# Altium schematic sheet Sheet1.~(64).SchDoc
size A3
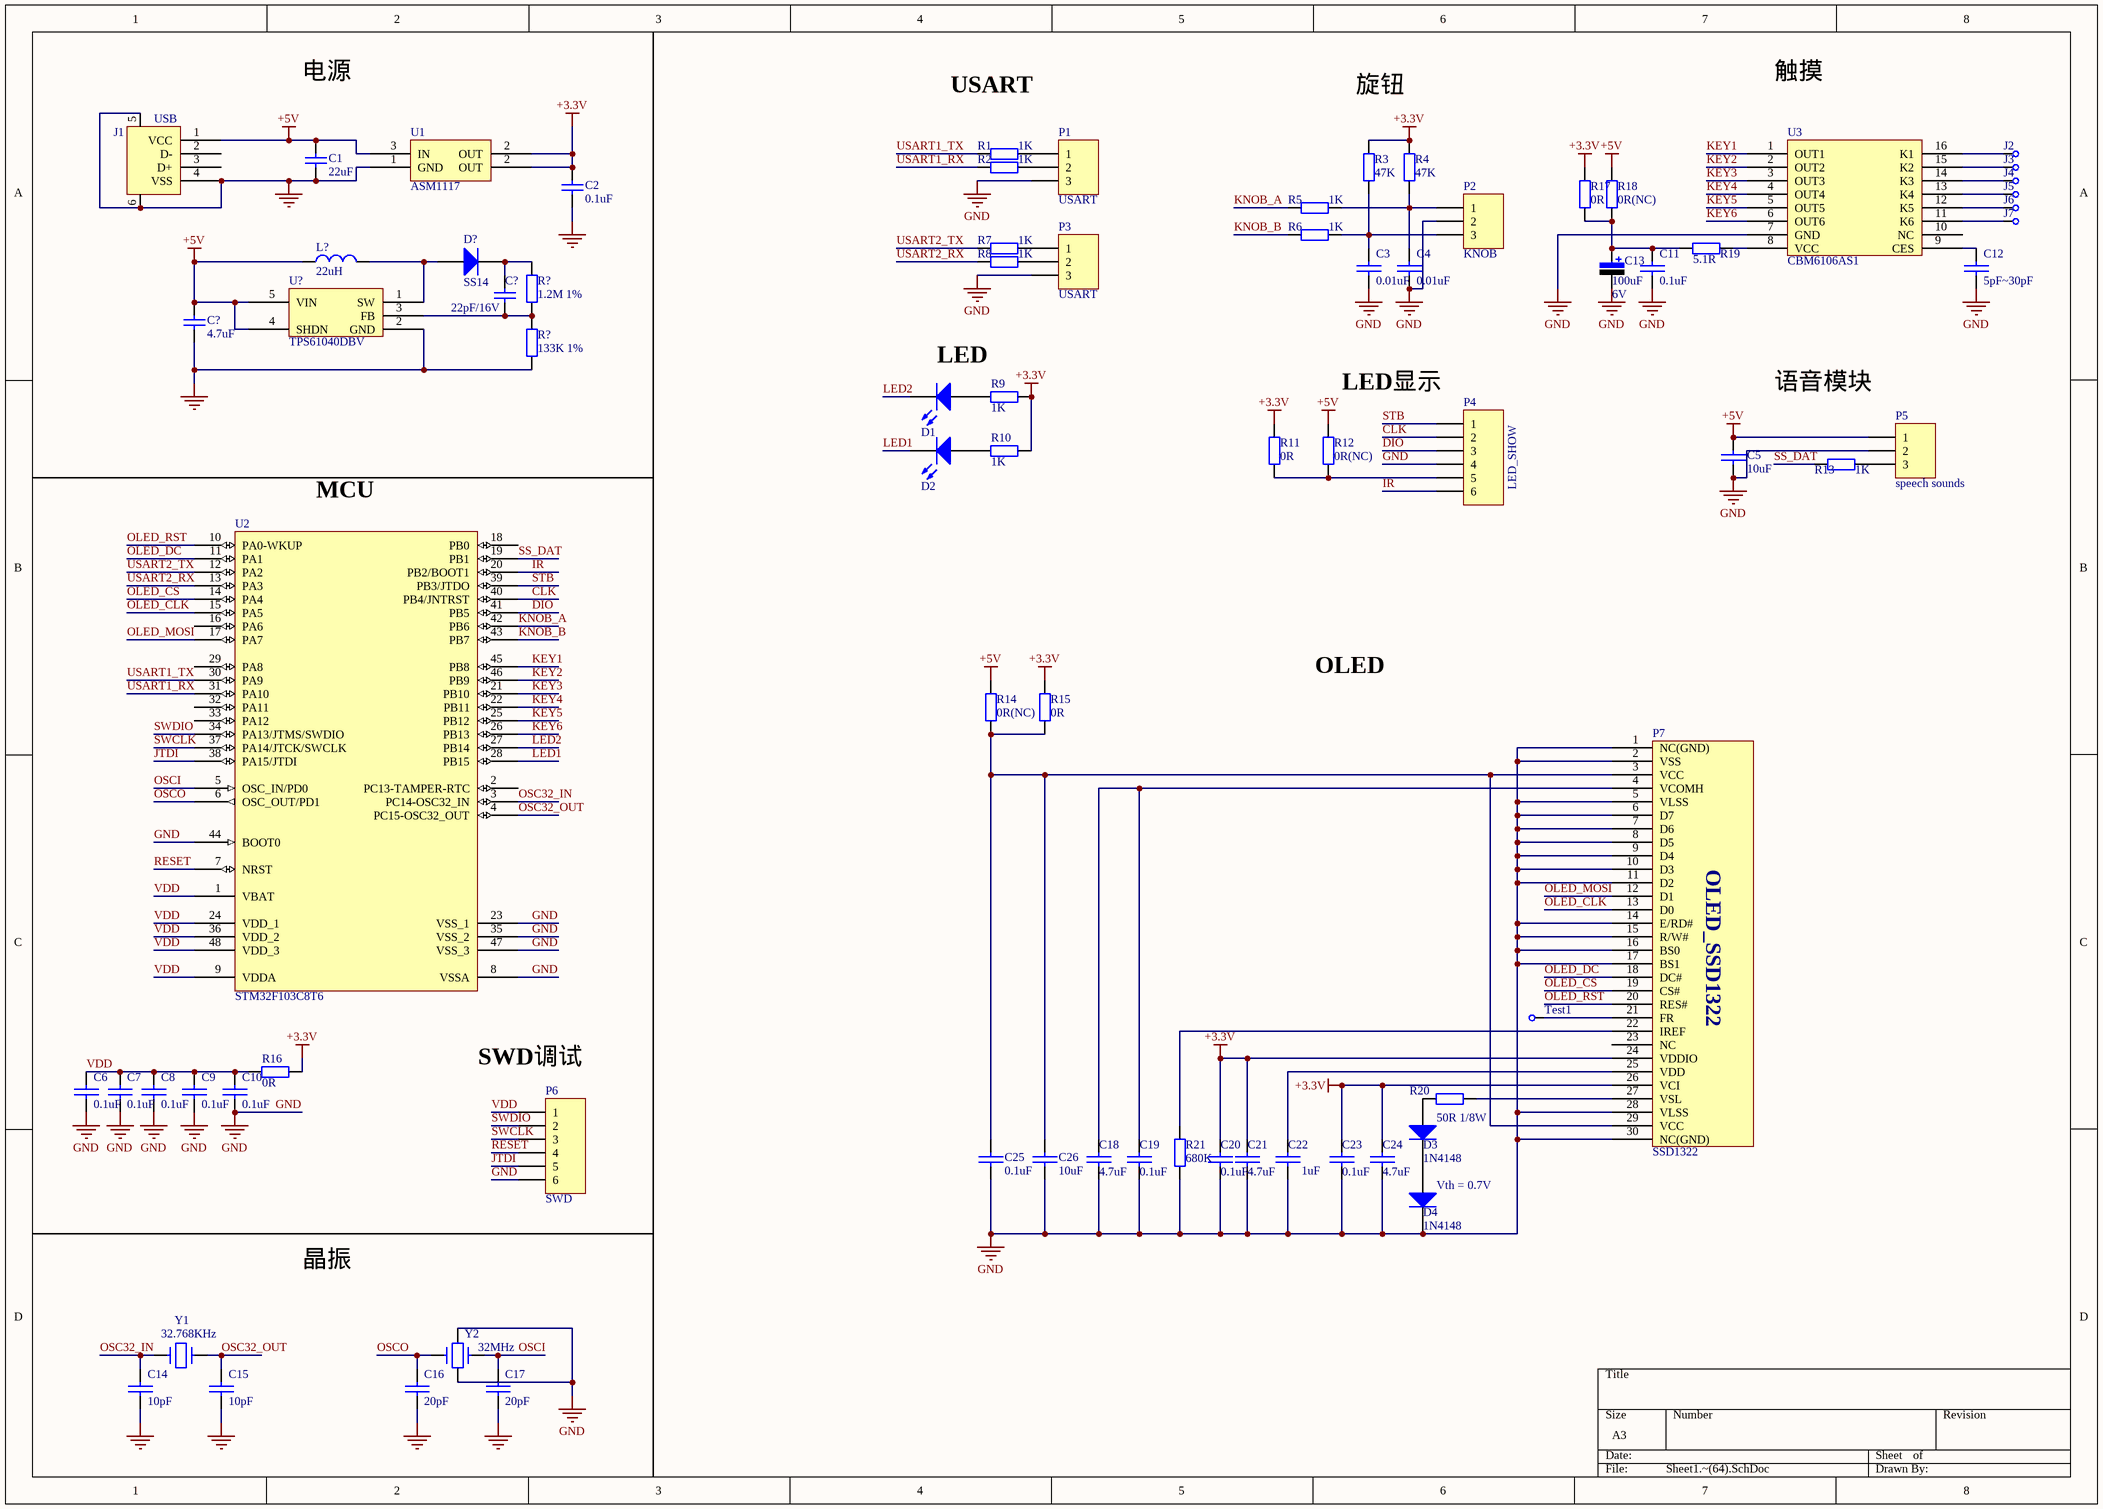
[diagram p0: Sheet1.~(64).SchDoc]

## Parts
(Parts that share a designator on the sheet are numbered #1, #2 ... from top to bottom, then left to right.)
C1  value 22uF  [0402C]  (hidden comment: Cap)
C2  value 0.1uF  [0402C]  (hidden comment: Cap)
C3  0.01uF  [0402C]
C4  0.01uF  [0402C]
C5  10uF  [0402C]
C6  0.1uF  [0402C]
C7  0.1uF  [0402C]
C8  0.1uF  [0402C]
C9  0.1uF  [0402C]
C10  0.1uF  [0402C]
C11  0.1uF  [0402C]
C12  5pF~30pF  [0402C]
C13  value 100uF  Vol: 6V  [CAP-3528]  (hidden comment: Cap Pol)
C14  10pF  [0402C]
C15  10pF  [0402C]
C16  20pF  [0402C]
C17  20pF  [0402C]
C18  4.7uF  [0402C]
C19  0.1uF  [0402C]
C20  0.1uF  [0402C]
C21  4.7uF  [0402C]
C22  1uF  [0402C]
C23  0.1uF  [0402C]
C24  4.7uF  [0402C]
C25  0.1uF  [0402C]
C26  10uF  [0402C]
C?#1  value 22pF/16V  [0402C]  (hidden comment: Cap)
C?#2  value 4.7uF  [0402C]  (hidden comment: Cap)
D1  LED0  [led0603]  (value not drawn)
D2  LED0  [led0603]  (value not drawn)
D3  Type: 1N4148  [DIODE-1206]  (hidden comment: Diode)
D4  Type: 1N4148  [DIODE-1206]  (hidden comment: Diode)
D?  Type: SS14  [DIODE-1206]  (hidden comment: Diode)
J1  USB  [USB_A1]
J2  CHECK  [CHECK-A]  (value not drawn)
J3  CHECK  [CHECK-A]  (value not drawn)
J4  CHECK  [CHECK-A]  (value not drawn)
J5  CHECK  [CHECK-A]  (value not drawn)
J6  CHECK  [CHECK-A]  (value not drawn)
J7  CHECK  [CHECK-A]  (value not drawn)
L?  value 22uH  [1206]  (hidden comment: Inductor)
P1  USART  [HDR3X1_A]
P2  KNOB  [HDR3X1_A]
P3  USART  [HDR3X1_A]
P4  LED_SHOW  [HDR6X1_B2]
P5  speech sounds  [HDR3X1_A]
P6  SWD  [HDR6X1_B2]
P7  SSD1322
R1  value 1K  [0402R]  (hidden comment: Res1)
R2  value 1K  [0402R]  (hidden comment: Res1)
R3  value 47K  [0603-1]  (hidden comment: Res1)
R4  value 47K  [0603-1]  (hidden comment: Res1)
R5  value 1K  [0603-1]  (hidden comment: Res1)
R6  value 1K  [0603-1]  (hidden comment: Res1)
R7  value 1K  [0402R]  (hidden comment: Res1)
R8  value 1K  [0402R]  (hidden comment: Res1)
R9  value 1K  [0402R]  (hidden comment: Res1)
R10  value 1K  [0402R]  (hidden comment: Res1)
R11  value 0R  [0402R]  (hidden comment: Res1)
R12  value 0R(NC)  [0402R]  (hidden comment: Res1)
R13  value 1K  [0402R]  (hidden comment: Res1)
R14  value 0R(NC)  [0402R]  (hidden comment: Res1)
R15  value 0R  [0402R]  (hidden comment: Res1)
R16  value 0R  [0402R]  (hidden comment: Res1)
R17  value 0R  [0402R]  (hidden comment: Res1)
R18  value 0R(NC)  [0402R]  (hidden comment: Res1)
R19  value 5.1R  [0603-1]  (hidden comment: Res1)
R20  value 50R 1/8W  [0402R]  (hidden comment: Res1)
R21  value 680K  [0402R]  (hidden comment: Res1)
R?#1  value 1.2M 1%  [0402R]  (hidden comment: Res1)
R?#2  value 133K 1%  [0402R]  (hidden comment: Res1)
Test1  CHECK  [CHECK-A]  (value not drawn)
U1  ASM1117  [SOT-223-3]
U2  STM32F103C8T6  [LQFP48_N]
U3  CBM6106AS1
U?  TPS61040DBV
Y1  32.768KHz  [SMD3215]
Y2  32MHz  [Y3225]

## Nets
+3.3V: C2.2 C20.1 C21.1 C23.1 C24.1 P7.24(VDDIO) P7.26(VCI) R3.2 R4.2 R9.1 R10.1 R11.1 R15.1 R16.2 R17.1 U1.2(OUT)
+5V: C1.2 C5.1 C?#2.2 J1.1(VCC) L?.1 P5.1 R12.1 R14.1 R18.1 U1.3(IN) U?.4(SHDN) U?.5(VIN)
GND: C1.1 C2.1 C3.2 C4.2 C5.2 C6.2 C7.2 C8.2 C9.2 C10.2 C11.2 C12.2 C13.2 C14.2 C15.2 C16.2 C17.2 C18.2 C19.2 C20.2 C21.2 C22.2 C23.2 C24.2 C25.1 C26.1 C?#2.1 D4.2(K) J1.4(VSS) J1.5 J1.6 P1.3 P2.2 P3.3 P4.4 P5.2 P6.6 P7.1(NC(GND)) P7.2(VSS) P7.5(VLSS) P7.6(D7) P7.7(D6) P7.8(D5) P7.9(D4) P7.10(D3) P7.11(D2) P7.14(E/RD#) P7.15(R/W#) P7.16(BS0) P7.17(BS1) P7.28(VLSS) P7.30(NC(GND)) R21.2 R?#2.2 U1.1(GND) U2.8(VSSA) U2.23(VSS_1) U2.35(VSS_2) U2.44(BOOT0) U2.47(VSS_3) U3.7(GND) U?.2(GND) Y2.2 Y2.4
CLK: P4.2 U2.40(PB4/JNTRST)
DIO: P4.3 U2.41(PB5)
IR: P4.6 U2.20(PB2/BOOT1)
JTDI: P6.5 U2.38(PA15/JTDI)
KEY1: U2.45(PB8) U3.1(OUT1)
KEY2: U2.46(PB9) U3.2(OUT2)
KEY3: U2.21(PB10) U3.3(OUT3)
KEY4: U2.22(PB11) U3.4(OUT4)
KEY5: U2.25(PB12) U3.5(OUT5)
KEY6: U2.26(PB13) U3.6(OUT6)
KNOB_A: R5.1 U2.42(PB6)
KNOB_B: R6.1 U2.43(PB7)
LED1: D2.2(K) U2.28(PB15)
LED2: D1.2(K) U2.27(PB14)
OLED_CLK: P7.13(D0) U2.15(PA5)
OLED_CS: P7.19(CS#) U2.14(PA4)
OLED_DC: P7.18(DC#) U2.11(PA1)
OLED_MOSI: P7.12(D1) U2.17(PA7)
OLED_RST: P7.20(RES#) U2.10(PA0-WKUP)
OSC32_IN: C14.1 U2.3(PC14-OSC32_IN) Y1.1
OSC32_OUT: C15.1 U2.4(PC15-OSC32_OUT) Y1.2
OSCI: C17.1 U2.5(OSC_IN/PD0) Y2.3
OSCO: C16.1 U2.6(OSC_OUT/PD1) Y2.1
RESET: P6.4 U2.7(NRST)
SS_DAT: R13.2 U2.19(PB1)
STB: P4.1 U2.39(PB3/JTDO)
SWCLK: P6.3 U2.37(PA14/JTCK/SWCLK)
SWDIO: P6.2 U2.34(PA13/JTMS/SWDIO)
USART1_RX: R2.2 U2.31(PA10)
USART1_TX: R1.2 U2.30(PA9)
USART2_RX: R8.2 U2.13(PA3)
USART2_TX: R7.2 U2.12(PA2)
VDD: C6.1 C7.1 C8.1 C9.1 C10.1 P6.1 R16.1 U2.1(VBAT) U2.9(VDDA) U2.24(VDD_1) U2.36(VDD_2) U2.48(VDD_3)
NetC3_1: C3.1 P2.3 R3.1 R6.2
NetC4_1: C4.1 P2.1 R4.1 R5.2
NetC11_1: C11.1 C13.1 R17.2 R18.2 R19.1
NetC12_1: C12.1 U3.9(CES)
NetC18_1: C18.1 C19.1 P7.4(VCOMH)
NetC22_1: C22.1 P7.25(VDD)
NetC25_2: C25.2 C26.2 P7.3(VCC) P7.29(VCC) R14.2 R15.2
NetC?#1_1: C?#1.1 R?#1.2 R?#2.1 U?.3(FB)
NetC?#1_2: C?#1.2 D?.2(K) R?#1.1
NetD1_1: D1.1(A) R9.2
NetD2_1: D2.1(A) R10.2
NetD3_1: D3.1(A) R20.2
NetD3_2: D3.2(K) D4.1(A)
NetD?_1: D?.1(A) L?.2 U?.1(SW)
NetJ2_1: J2.1 U3.16(K1)
NetJ3_1: J3.1 U3.15(K2)
NetJ4_1: J4.1 U3.14(K3)
NetJ5_1: J5.1 U3.13(K4)
NetJ6_1: J6.1 U3.12(K5)
NetJ7_1: J7.1 U3.11(K6)
NetP1_1: P1.1 R1.1
NetP1_2: P1.2 R2.1
NetP3_1: P3.1 R7.1
NetP3_2: P3.2 R8.1
NetP4_5: P4.5 R11.2 R12.2
NetP5_3: P5.3 R13.1
NetP7_21: P7.21(FR) Test1.1
NetP7_22: P7.22(IREF) R21.1
NetP7_27: P7.27(VSL) R20.1
NetR19_2: R19.2 U3.8(VCC)

Not connected (* = marked no-connect by the designer): J1 2(D-) 3(D+); P7 23(NC); U2 2(PC13-TAMPER-RTC) 16(PA6) 18(PB0) 29(PA8) 32(PA11) 33(PA12); U3 10(NC)

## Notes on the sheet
- 电源
- USART
- 旋钮
- 触摸
- LED
- LED显示
- 语音模块
- (near U2) MCU
- OLED
- (near P6) SWD调试
- (near D4) Vth = 0.7V
- 晶振

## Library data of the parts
C1 C2 C?#1 C?#2 = Cap: 无极性电容
C3-C12 C14-C26 = CAP: Capacitor
C13 = Cap Pol: 极性电解电容
D1 D2 = LED0: 发光二极管
D3 D4 D? = Diode: 二极管
J1 = USB: USB接口
J2-J7 Test1 = CHECK: 测试点
L? = Inductor: 电感; Code_IEC: 1005
P1-P3 P5 = Header 3: 接插件
P4 P6 = Header 6: 接插件
R1-R21 R?#1 R?#2 = Res1: 贴片电阻
U1 = ASM1117: 3.3V稳压芯片
U2 = STM32F103C8T6: STM32 ARM-based 32-bit MCU with 64 Kbytes Flash, 48-pin LQFP, Industrial Temperature
Y1 = CRYSTAL
Y2 = CRYSTAL1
